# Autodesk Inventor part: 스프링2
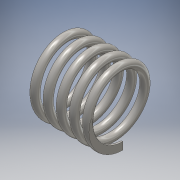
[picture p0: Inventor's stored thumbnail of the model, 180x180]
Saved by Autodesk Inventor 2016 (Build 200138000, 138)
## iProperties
Created: 2019-11
Part Number: 스프링2
Material: 스테인레스 스틸
Document SubType Name: Modeling
Designer: user
Density: 8 g/cm^3
Appearance: 반연마
Mass: 6.55014 g
Surface Area: 16.6978 cm^2
Volume: 0.818768 cm^3
Author: user
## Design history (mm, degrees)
sketch "스케치2"
  geometry: L1 (0, 0)-(17.5, 0); L2 (17.5, 0)-(17.5, -8.5); L3 (17.5, -8.5)-(0, -8.5); L4 (0, -8.5)-(0, 0); C1 r 1 at (0, -8.5)
  constraints: 8 end point, 2 parallel, 1 centre point, 1 coincident, 1 horizontal, 1 perpendicular
  dimensions: "d0" = 17 diameter of L3 L1; "d1" = 17.5 distance between parallel lines of L4 L2 (derived); "d2" = 2 diameter of C1
feature "코일1" sketch "스케치2" pitch "d3" = 10; turns "d5" = 5; dims "d4" = 17.5 (= d1), "d6" = 0, angle "d7" = 90 deg, angle "d8" = 90 deg, "d9" = 0, "d10" = 0
sketch "스케치3"
  geometry: L1 (0, -15)-(-17.5, -15); L2 (-17.5, -15)-(-17.5, 15); L3 (-17.5, 15)-(0, 15); L4 (0, 15)-(0, -15); 2 further points
  constraints: 8 end point, 2 parallel, 1 coincident, 1 horizontal, 1 midpoint, 1 perpendicular
  dimensions: "d11" = 17.5 distance of L2.end L3.end (= d1); "d12" = 30 distance of L1.end L2.end
extrude "돌출1" sketch "스케치3" stored distance "d13" = 42.75; taper "d14" = 0 deg
node "솔리드1"
